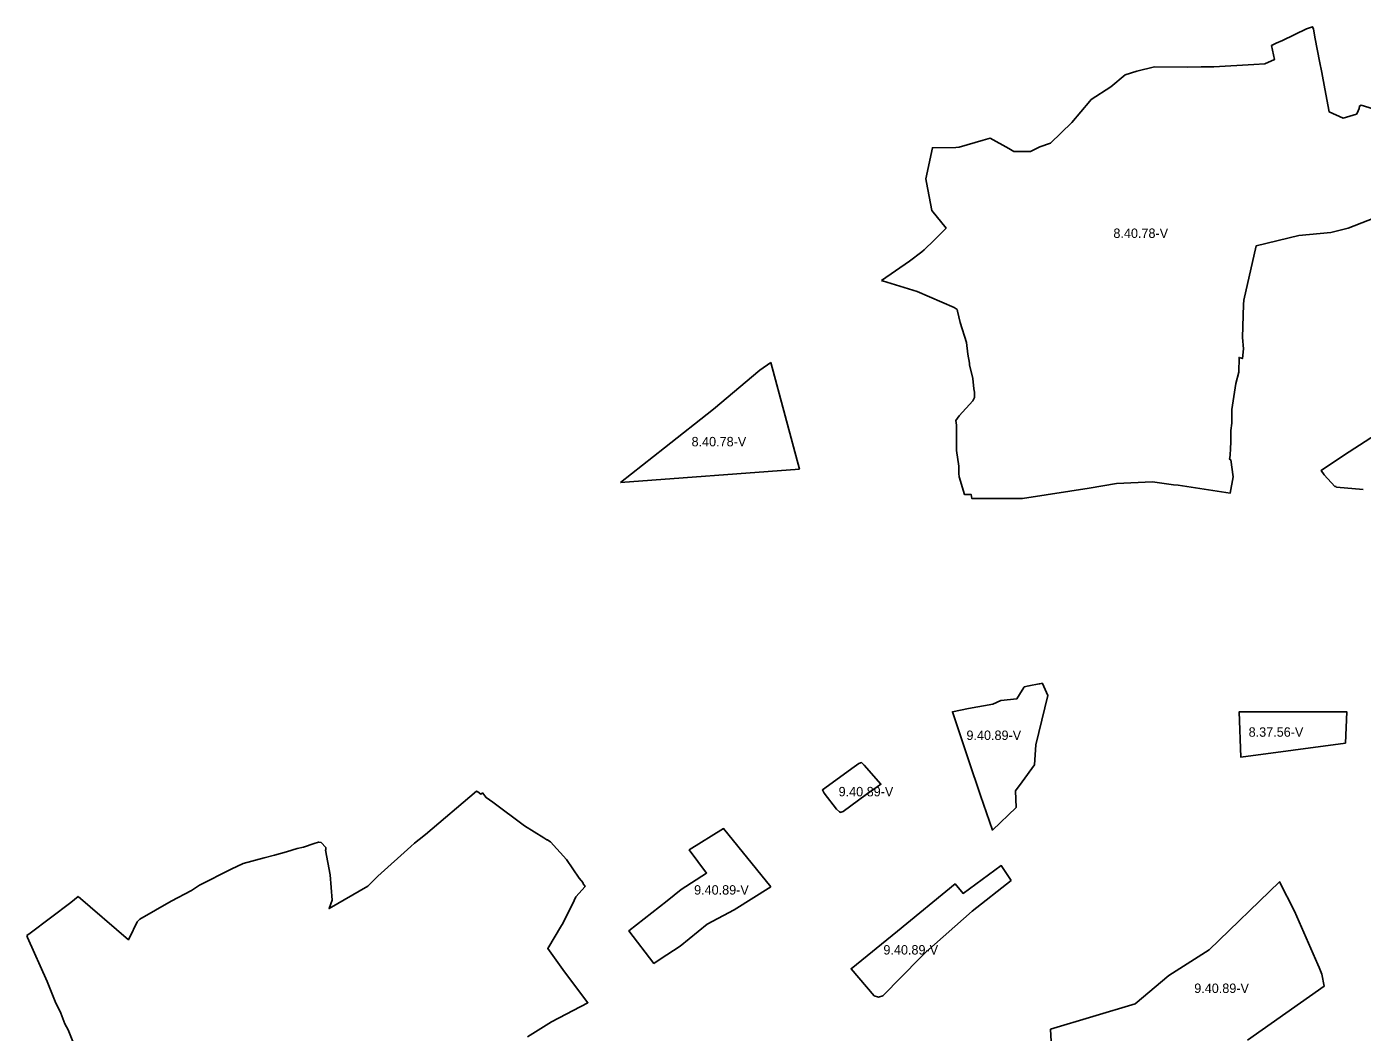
# Model space of a CAD drawing. Extents: x -444937 to -440470, y -1149084 to -1129741.
# Drawn here: x -444703 to -443286, y -1132888 to -1131821 of the extents above; entities that cross this region are included whole.
import ezdxf

# ---------------------------------------------------------------- set-up
doc = ezdxf.new("R2010")
doc.units = 0
doc.layers.add('Vrstva 28', color=7, linetype='Continuous')

msp = doc.modelspace()

# ---------------------------------------------------------------- linework, layer by layer
at = {"layer": 'Vrstva 28'}
for points in [[(-443382.72, -1131841.27), (-443381.81, -1131840.87), (-443377.69, -1131839.05), (-443371.04, -1131836.11), (-443345.53, -1131823.57), (-443339.15, -1131821.44), (-443338.09, -1131824.21), (-443336.28, -1131834.14), (-443331.92, -1131858.01)], [(-443796.04, -1132090.7), (-443766.44, -1132070.14), (-443753.38, -1132060.18), (-443751.12, -1132058), (-443740.49, -1132047.74), (-443727.75, -1132035.14), (-443742.79, -1132016.22), (-443748.48, -1131986.52), (-443749.19, -1131982.83), (-443742.21, -1131949.8), (-443717.48, -1131949.61), (-443713.85, -1131949.02), (-443688.48, -1131941.73), (-443680.94, -1131939.56), (-443661.32, -1131950.66), (-443655.99, -1131953.67), (-443638.18, -1131953.77), (-443628.48, -1131948.87), (-443616.95, -1131944.89), (-443594.49, -1131922.99), (-443575.38, -1131900.47), (-443573.87, -1131898.7), (-443552.93, -1131885.12), (-443537.86, -1131872.43), (-443525.54, -1131868.7), (-443506.55, -1131863.91), (-443472.08, -1131864.36), (-443457.23, -1131864.14), (-443443.78, -1131863.94), (-443401.34, -1131861.39), (-443389.59, -1131860.69), (-443379.47, -1131856.15), (-443382.72, -1131841.27)], [(-443331.92, -1131858.01), (-443329.16, -1131869.91), (-443326.01, -1131887.21), (-443321.55, -1131911.68), (-443306.84, -1131918.38), (-443292.59, -1131914.34), (-443291.98, -1131912.98), (-443289.83, -1131908.18), (-443289.41, -1131905.63), (-443287.71, -1131904.56), (-443274.76, -1131908.41)], [(-443266.19, -1132021.29), (-443301.34, -1132034.98), (-443319.81, -1132039.52), (-443353.77, -1132042.93), (-443398.86, -1132053.65), (-443412.06, -1132111.57), (-443412.21, -1132116.01), (-443413.4, -1132150.96), (-443412.21, -1132163.06), (-443413.48, -1132173.3), (-443417.04, -1132172.14), (-443417.37, -1132187.95), (-443420.56, -1132199.87), (-443424.61, -1132227.54), (-443424.61, -1132242.02), (-443425.88, -1132249.68), (-443425.67, -1132262.45), (-443426.04, -1132268.44), (-443426.52, -1132276.08), (-443427.02, -1132280.09), (-443425.94, -1132280.84), (-443423.37, -1132298.64), (-443426.36, -1132315.95), (-443481.58, -1132307.75), (-443486.45, -1132307.08), (-443508.99, -1132303.97), (-443547.08, -1132305.96), (-443576.09, -1132310.62), (-443596.61, -1132313.86), (-443646.84, -1132321.8), (-443677.53, -1132321.8), (-443700.38, -1132321.79), (-443701.26, -1132317.46), (-443708.35, -1132317.37), (-443713.67, -1132298.85), (-443714.1, -1132295.23), (-443714.1, -1132287.57), (-443716.65, -1132270.97), (-443716.65, -1132244.15), (-443717.5, -1132239.04), (-443713.89, -1132233.93), (-443699.41, -1132218.18), (-443697.5, -1132214.77), (-443697.5, -1132208.81), (-443698.35, -1132205.41), (-443699.2, -1132194.34), (-443703.03, -1132179.86), (-443702.82, -1132178.16), (-443704.73, -1132168.79), (-443706.01, -1132156.45), (-443712.61, -1132135.16), (-443715.62, -1132122.93), (-443716.02, -1132121.33), (-443718.99, -1132119.2), (-443758.37, -1132102.17), (-443795.01, -1132091.01), (-443795.56, -1132090.84), (-443796.04, -1132090.7)], [(-444073.03, -1132304.67), (-444026.24, -1132267.99), (-443974.18, -1132227.02), (-443925.28, -1132185.67), (-443913.53, -1132177.67)], [(-443913.53, -1132177.67), (-443883.08, -1132290.8)], [(-443285.39, -1132312.15), (-443313.66, -1132309.79), (-443314.35, -1132308.95), (-443315.41, -1132308.86), (-443326.9, -1132296.51), (-443330.16, -1132292.18), (-443306.47, -1132276.08), (-443254.53, -1132242.66)], [(-443883.08, -1132290.8), (-444073.03, -1132304.67)], [(-443691.07, -1132636.53), (-443703.78, -1132598.97), (-443721.08, -1132547.83), (-443703.88, -1132544.56), (-443678.13, -1132539.95), (-443669.74, -1132536.12), (-443652.62, -1132534.18), (-443649.7, -1132529.42), (-443645.15, -1132522.03), (-443644.87, -1132521.58), (-443639.81, -1132520.57), (-443629.1, -1132518.43), (-443628.95, -1132518.31), (-443628.96, -1132518.4), (-443628.29, -1132518.27), (-443625.48, -1132517.7), (-443625.32, -1132518.07)], [(-443625.32, -1132518.07), (-443619.99, -1132530.63), (-443632.65, -1132583.09), (-443633.86, -1132604.35), (-443647.09, -1132622.27), (-443654.17, -1132631.61), (-443653.44, -1132649.34), (-443678.64, -1132673.29), (-443691.07, -1132636.53)], [(-443304.36, -1132581.27), (-443415.19, -1132596.01), (-443417.08, -1132548.13), (-443302.82, -1132547.92), (-443304.36, -1132581.27)], [(-443839.03, -1132654.4), (-443839.48, -1132654.55), (-443840.75, -1132654.12), (-443843.95, -1132651.14), (-443856.93, -1132634.11), (-443857.64, -1132632.93), (-443858.89, -1132630.83), (-443825.06, -1132606.26), (-443820.32, -1132602.82), (-443817.55, -1132601.76), (-443814.59, -1132604.51)], [(-443814.59, -1132604.51), (-443796.74, -1132624.8), (-443800.7, -1132627.58), (-443812.33, -1132635.76), (-443836.92, -1132653.69), (-443839.03, -1132654.4)], [(-444647.91, -1132743.8), (-444594.68, -1132789.68), (-444593.86, -1132788.01), (-444593.61, -1132787.5), (-444585.35, -1132770.77), (-444582.58, -1132768), (-444549.37, -1132748.63), (-444527.87, -1132737.35), (-444519.36, -1132731.82), (-444485.94, -1132714.79), (-444473.17, -1132708.83), (-444450.83, -1132702.83), (-444439.9, -1132699.92), (-444426.98, -1132696.48), (-444415.91, -1132692.86), (-444409.1, -1132691.58), (-444397.69, -1132687.63), (-444393.13, -1132686.05), (-444390.36, -1132686.69), (-444385.47, -1132691.8), (-444385.25, -1132694.35), (-444385.8, -1132694.62), (-444380.62, -1132720.86), (-444378.83, -1132747.8), (-444381.88, -1132756.55), (-444340.98, -1132732.88), (-444330.12, -1132722.24), (-444295.43, -1132690.73), (-444291.27, -1132687.42), (-444286.32, -1132683.47), (-444279.67, -1132678.17), (-444225.5, -1132632.11), (-444224.22, -1132632.98)], [(-444224.22, -1132632.98), (-444220.89, -1132635.24), (-444219.31, -1132633.87), (-444215.52, -1132638.89), (-444208.15, -1132643.9), (-444174.89, -1132668.71), (-444154.07, -1132681.58), (-444150.89, -1132683.55), (-444150.25, -1132683.71), (-444149.86, -1132684.19), (-444147.04, -1132685.93), (-444130.22, -1132704.39), (-444116.64, -1132724.28), (-444112.57, -1132729.2), (-444112.87, -1132729.8), (-444110.55, -1132733.21), (-444120.13, -1132744.26), (-444122.09, -1132748.17), (-444132.8, -1132769.5), (-444134.72, -1132773.32), (-444135.66, -1132774.39), (-444150, -1132798.87), (-444132.24, -1132823.55), (-444107.5, -1132856.45), (-444146, -1132876.67), (-444171.45, -1132892.73)], [(-444030.76, -1132810.19), (-444037.53, -1132814.75), (-444064.09, -1132780.05), (-444023.49, -1132748.27), (-444008.45, -1132736.5), (-443981.66, -1132719.02), (-444000.12, -1132694.41), (-443963.72, -1132671.86), (-443913.62, -1132733.42)], [(-443700, -1132759.4), (-443749.2, -1132803), (-443755.13, -1132808.98), (-443794.9, -1132849.1), (-443799.3, -1132850.7), (-443803.8, -1132849.1), (-443828.38, -1132820.41), (-443779.38, -1132780.42), (-443718.1, -1132730.4), (-443709.7, -1132740.5), (-443669.3, -1132711), (-443658.8, -1132726.7)], [(-443913.62, -1132733.42), (-443952.43, -1132757.99), (-443980.91, -1132773.22), (-444009.65, -1132796.43), (-444030.76, -1132810.19)], [(-443658.8, -1132726.7), (-443700, -1132759.4)], [(-443572.9, -1132938.2), (-443581.63, -1132942.44), (-443596.87, -1132946.92), (-443599.01, -1132939.92), (-443601.31, -1132932.37), (-443611.5, -1132935.48), (-443614.24, -1132936.31), (-443616.98, -1132884.53), (-443527.16, -1132857.75), (-443491.66, -1132827.42), (-443448.67, -1132800.47), (-443374.21, -1132728.14), (-443358.28, -1132759.18), (-443333.67, -1132815.95), (-443332.23, -1132819.25), (-443329.25, -1132826.13), (-443326.96, -1132839.03), (-443408.25, -1132896.1)], [(-444702.56, -1132785.28), (-444699.06, -1132782.65), (-444655.83, -1132750.08), (-444647.91, -1132743.8)], [(-444636.01, -1132938.93), (-444637.5, -1132937.44), (-444649.42, -1132908.36), (-444649.58, -1132907.98), (-444650.87, -1132904.79), (-444658.78, -1132885.29), (-444662.19, -1132878.9), (-444666.45, -1132867.41), (-444672.41, -1132855.06), (-444680.92, -1132833.78), (-444701.78, -1132787.37), (-444702.56, -1132785.28)]]:
    msp.add_lwpolyline(points, dxfattribs=at)

# ---------------------------------------------------------------- texts
for s, p in [('8.40.78-V', (-443550.29, -1132045.44)), ('8.40.78-V', (-443997.6, -1132266.44)), ('9.40.89-V', (-443706.11, -1132577.83)), ('8.37.56-V', (-443406.88, -1132574.39)), ('9.40.89-V', (-443841.65, -1132637.58)), ('9.40.89-V', (-443994.9, -1132741.81)), ('9.40.89-V', (-443794.17, -1132805.34)), ('9.40.89-V', (-443464.57, -1132846.1))]:
    msp.add_text(s, height=10, dxfattribs=at).set_placement(p)

doc.saveas('drawing.dxf')
